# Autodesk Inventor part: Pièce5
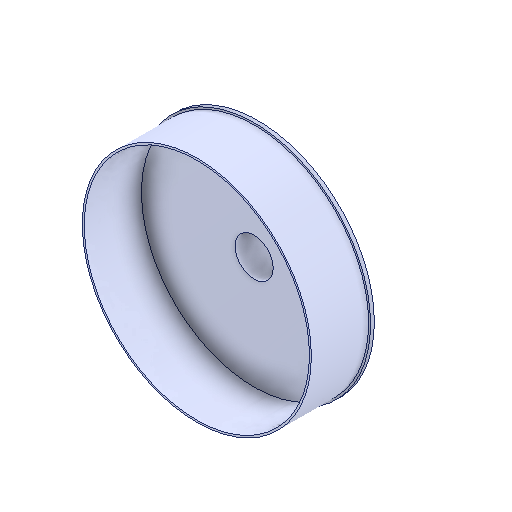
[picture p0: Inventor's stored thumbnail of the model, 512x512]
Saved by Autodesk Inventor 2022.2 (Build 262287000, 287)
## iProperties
Created: 2016-10
Part Number: Pièce5
Material: Generico
Document SubType Name: Modeling
Designer: 18907419
Density: 1 g/cm^3
Appearance: Default
Author: 18907419
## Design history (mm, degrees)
feature "Solido1"
node "Solido2"
